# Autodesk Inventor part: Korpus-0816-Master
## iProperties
Manager: Dr.-Ing. Roland Schröder
Company: www.Das-Entwicklungsbuero.de
Created: 2006-09
Part Number: Korpus-0816-Master
Project: 12107
Document SubType Name: Modeling
Designer: rsc
Engineer: Dr.-Ing. Roland Schröder
Author: rsc
b: 650,000 mm
d: 150,000 mm
a: 300,000 mm
Kanten: brechen
Oberflächen: Ra 6,4
Toleranzen: ISO 2768 - m
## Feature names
1. Extrusion2
2. Wandstärke1
